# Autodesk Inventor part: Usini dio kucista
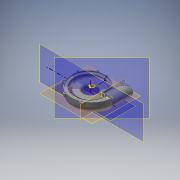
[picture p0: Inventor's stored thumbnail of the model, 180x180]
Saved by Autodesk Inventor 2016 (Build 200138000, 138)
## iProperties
Created: 2015-03
Part Number: Usini dio kucista
Material: Generic
Document SubType Name: Modeling
Designer: Uglješa
Density: 1 g/cm^3
Appearance: Default
Mass: 1245.57 g
Surface Area: 2848.36 cm^2
Volume: 1245.57 cm^3
Author: Uglješa
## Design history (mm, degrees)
sketch "Sketch1"
  geometry: L1 (0, 36.378)-(0, -65.866) reference; L2 (105, -10)-(105, 10); L3 (105, 10)-(102, 10); L4 (102, 10)-(102, 2); L5 (102, 2)-(90, 2); L6 (90, 2)-(90, -2); L7 (51.654, -17)-(51.654, -12); L8 (51.654, -17)-(80, -17); L9 (83.626, -12)-(51.654, -12); A1 r 13.48 centre (91.52, -10) between (80, -17) and (105, -10); A2 r 8.143 centre (91.52, -10) between (83.626, -12) and (90, -2); 1 further point
  constraints: 18 end point, 4 point on circle, 3 perpendicular, 2 centre point, 1 coincident, 1 horizontal, 1 parallel, 1 tangent, 1 vertical
  dimensions: "d25" = 8 distance between parallel lines of L3 L5; "d28" = 10 vertical distance of point (0, 0) A1.centre; "d151" = 12 distance from line of point (0, 0) L9; "d152" = 5 distance between parallel lines of L8 L9; "d344" = 15 distance between parallel lines of L6 L2; "d365" = 210 diameter of L2 L1; "d509" = 2 distance from line of point (0, 0) L5; "d514" = 4 distance of L5.end L6.end; "d616" = 25 distance from line of L2 L8.end; "d670" = 3 distance of L2.end L3.end
sketch "Sketch2"
  geometry: L1 (53.134, -17)-(80, -17); L2 (0, 0)-(0, -94.804) reference; L3 (53.134, -12)-(86.237, -12); L4 (120, -16)-(120, -0.062); L5 (103, -2)-(103, 2); L6 (117, 10)-(120, 10); L7 (120, 10)-(120, -0.062); L8 (53.134, -12)-(53.134, -17); L9 (117, 10)-(117, 2); L10 (117, 2)-(103, 2); A1 r 14.32 centre (99.987, -16) between (86.237, -12) and (103, -2); A2 r 20.013 centre (99.987, -16) between (80, -17) and (120, -16)
  constraints: 20 end point, 4 point on circle, 3 perpendicular, 2 centre point, 1 coincident, 1 collinear, 1 parallel, 1 tangent, 1 vertical
  dimensions: "d39" = 12 distance from line of L3 L2.start; "d42" = 5 distance between parallel lines of L3 L1; "d50" = 16 vertical distance of L2.start A1.centre; "d184" = 17 distance between parallel lines of L7 L5; "d350" = 2 distance from line of L2.start L10; "d351" = 8 distance between parallel lines of L6 L10; "d364" = 240 diameter of L4 L2; "d513" = 4 distance of L5.start L5.end; "d617" = 40 distance from line of L4 L1.end; "d671" = 3 distance of L6.start L6.end
sketch "Sketch3"
  geometry: L1 (0, -126.8)-(0, 28.645) reference; L2 (-61.778, -17)-(-75, -17); L3 (-61.778, -12)-(-84.03, -12); L4 (-130, -22)-(-130, 10); L5 (-108, -2)-(-108, 2); L6 (-108, 2)-(-127, 2); L7 (-127, 2)-(-127, 10); L8 (-127, 10)-(-130, 10); L9 (-61.778, -12)-(-61.778, -17); A1 r 27.727 centre (-102.273, -22) between (-130, -22) and (-75, -17); A2 r 20.804 centre (-102.273, -22) between (-108, -2) and (-84.03, -12); 1 further point
  constraints: 18 end point, 4 point on circle, 3 perpendicular, 3 vertical, 2 centre point, 2 parallel, 1 coincident, 1 tangent
  dimensions: "d62" = 5 distance between parallel lines of L2 L3; "d64" = 12 distance from line of point (0, 0) L3; "d70" = 8 distance of L6.end L7.end; "d72" = 2 distance from line of L6 point (0, 0); "d74" = 22 vertical distance of point (0, 0) A1.centre; "d186" = 22 distance between parallel lines of L4 L5; "d368" = 260 diameter of L4 L1; "d515" = 4 distance of L5.start L5.end; "d618" = 55 distance from line of L4 L2.end; "d678" = 3 distance of L7.end L4.end
sketch "Sketch4"
  geometry: L1 (0, 0)-(0, 390.533); L2 (0, 0)-(-377.579, 0); L3 (-120, 0)-(-120, -351.799); L4 (0, 105)-(221.176, 105); A1 r 105.938 centre (-14.063, 0) between (0, 105) and (-120, 0)
  constraints: 8 end point, 2 point on circle, 2 point on line, 2 vertical, 1 centre point, 1 horizontal, 1 perpendicular, 1 tangent
  dimensions: "d359" = 105 distance of L4.start L1.start; "d363" = 120 distance of L3.start L1.start
sketch "Sketch7"
  geometry: L1 (0, 0)-(0, -210.072); L2 (-140, -30)-(-140, 10); L3 (-140, 10)-(-137, 10); L4 (-137, 10)-(-137, 2); L5 (-137, 2)-(-106.2, 2); L6 (-106.2, 2)-(-106.2, -2); L7 (-84.752, -12)-(-48.748, -12); L8 (-48.748, -12)-(-48.748, -17); L9 (-48.748, -17)-(-75, -17); A1 r 33.8 centre (-106.2, -30) between (-140, -30) and (-75, -17); A2 r 28 centre (-106.2, -30) between (-106.2, -2) and (-84.752, -12)
  constraints: 18 end point, 4 parallel, 4 point on circle, 3 perpendicular, 2 centre point, 2 vertical, 1 coincident, 1 point on line, 1 tangent
  dimensions: "d102" = 8 distance of L3.end L4.end; "d103" = 28 radius of A2; "d207" = 2 vertical distance of L1.start L6.end; "d209" = 5 distance of L7.end L8.end; "d210" = 12 distance from line of L1.start L7; "d375" = 280 diameter of L2 L1; "d516" = 22 distance between parallel lines of L3 L7; "d619" = 65 distance from line of L9.end L2; "d679" = 3 distance of L2.end L3.end
loft "Loft4" dims "d672" = 10, "d673" = 90 deg, "d674" = 10, "d675" = 90 deg, "d676" = 0, "d677" = 90 deg
sketch "Sketch11"
  geometry: L1 (40, -27)-(40, -39.604); L2 (50, -42)-(55, -42); L3 (55, -42)-(55, -22); L4 (60, -17)-(77.651, -17); L5 (55, -12)-(77.651, -12); L6 (0, 0)-(0, -85.323); L7 (77.651, -17)-(77.651, -12); L8 (50, -60)-(48, -60); L9 (50, -60)-(50, -42); A1 r 30 centre (70, -39.604) between (40, -39.604) and (48, -60); A2 r 15 centre (55, -27) between (55, -12) and (40, -27); A3 r 5 centre (60, -22) between (60, -17) and (55, -22); 1 further point
  constraints: 18 end point, 6 point on circle, 5 tangent, 3 centre point, 2 parallel, 2 perpendicular, 2 point on line, 2 vertical, 1 horizontal
  dimensions: "d136" = 5 distance between parallel lines of L5 L4; "d138" = 15 radius of A2; "d139" = 80 diameter of L1 L6; "d141" = 30 radius of A1; "d144" = 17 distance from line of L6.start L4; "d193" = 5 radius of A3; "d414" = 18 distance between parallel lines of L2 L8; "d416" = 100 diameter of L9 L6; "d417" = 42 distance from line of L6.start L2; "d418" = 2 distance of L8.start L8.end; "d662" = 5 distance between parallel lines of L9 L3
sketch "Sketch12"
  geometry: L1 (-120, 0)-(-120, 196.1); L2 (0, 0)-(0, 238.053); A1 r 130.417 centre (10.417, 0) between (-120, 0) and (0, -130)
  constraints: 4 end point, 2 point on circle, 2 vertical, 1 centre point, 1 point on line, 1 tangent
  dimensions: "d369" = 130 distance of A1.end L2.start; "d370" = 120 distance of L2.start L1.start; "d371" = 120 distance from line of L2.start L1
loft "Loft5" sketch "Sketch12" dims "d187" = 0, "d188" = 90 deg, "d189" = 0, "d190" = 90 deg, "d372" = 0, "d373" = 90 deg
sketch "Sketch13"
  geometry: L1 (0, 0)-(185.048, 0); L2 (0, 0)-(0, -182.275); L3 (0, 0)-(487.793, 0); L4 (0, 0)-(0, -482.564); L5 (140, 0)-(140, 388.334); A1 r 130.357 centre (9.643, 0) between (0, -130) and (140, 0); 2 further points
  constraints: 10 end point, 4 point on line, 2 horizontal, 2 point on circle, 2 vertical, 1 centre point, 1 perpendicular, 1 tangent
  dimensions: "d376" = 140 distance of L1.start L5.start; "d377" = 130 distance of L1.start A1.start
workplane "Work Plane3"
workplane "Work Plane6"
sketch "Sketch34"
  geometry: L1 (113.093, 65.922)-(96.417, 49.246); L2 (47.171, 85.264)-(47.171, 65.141); L3 (92.893, -45.721)-(111.926, -64.755); L4 (47.171, -67.337)-(47.171, -94.636); L5 (-0.858, -48.029)-(-16.786, -63.958); L6 (47.171, 0)-(331.223, 0); L7 (-2.517, 49.689)-(1.756, 45.416); L8 (-27.461, 0)-(-54.951, 0); L9 (47.171, 0)-(-109.659, 0); L10 (144.214, 0)-(113.093, 0)
  constraints: 20 end point, 9 point on line, 2 horizontal, 2 perpendicular, 1 vertical
  dimensions: "d262" = 45 deg angle of L1 L6; "d263" = 45 deg angle of L1 L2; "d264" = 45 deg angle of L5 L4; "d265" = 45 deg angle of L2 L7
loft "Loft8" dims "d378" = 0, "d379" = 90 deg, "d380" = 0, "d381" = 90 deg, "d382" = 0, "d383" = 90 deg
  node "Edges3"
revolve "Revolution3" stored, may be unused: angle "d419" = 90 deg
sketch "Sketch55"
  geometry: L1 (55, -22)-(55, -42) reference; L2 (55, -30)-(102.194, -23.367); L3 (55, -30)-(55, -22); L4 (55, -22)-(100, -22); A1 r 15 centre (109, -10) between (100, -22) and (119.658, -20.555) reference; A2 r 15 centre (109, -10) between (100, -22) and (102.194, -23.367); 1 further point
  constraints: 6 end point, 3 point on circle, 1 centre point, 1 concentric, 1 horizontal, 1 point on line, 1 vertical
  dimensions: "d460" = 8 distance from line of L4 L2.start; "d461" = 8 deg angle of L4 L2
workplane "Work Plane14"
fillet "Fillet22" dims "d480" = 2
chamfer "Chamfer2" distance "d481" = 2; stored, may be unused: second distance "d482" = 2, angle "d483" = 45 deg
workplane "Work Plane15"
sketch "Sketch59"
  geometry: L1 (0, 0)-(0, 270.285); L2 (0, 0)-(203.327, 0); L3 (140, 0)-(139.966, 78); L4 (139.966, 78)-(141.966, 80); L5 (736.882, 1.819)-(736.828, 125); L6 (106.2, 0)-(106.2, 152.997); L7 (137.474, 120)-(144.101, 120); L8 (139.759, 105)-(145.151, 105); L9 (78.2, 0)-(134.2, 0) reference; L10 (134.2, 0)-(134.2, 130); L11 (134.2, 130)-(141.944, 130); L12 (141.966, 80)-(141.956, 102.042); L13 (141.954, 107.958)-(141.95, 117.042); L14 (141.947, 122.958)-(141.944, 130); L15 (134.2, 0)-(140, 0); A1 r 3 centre (142.448, 120) between (141.947, 122.958) and (141.95, 117.042); A2 r 3 centre (142.455, 105) between (141.954, 107.958) and (141.956, 102.042); 3 further points; 1 other entity
  constraints: 28 end point, 5 parallel, 4 point on circle, 3 collinear, 3 vertical, 2 centre point, 2 point on line, 1 horizontal, 1 midpoint, 1 perpendicular, 2 other
  dimensions: "d492" = 2 horizontal distance of L3.end L4.end; "d493" = 2 horizontal distance of L3.end L4.end; "d495" = 250 diameter of L5.end L2; "d623" = 3 radius of A2; "d624" = 3 radius of A1; "d629" = 130 distance from line of L11 L3.start; "d631" = 0 deg angle of L11 L7; "d632" = 10 distance from line of L11 L7.end; "d633" = 25 distance from line of L11 L8.end; "d634" = 50 distance from line of L11 L4.end; "d635" = 0.5 distance from line of L13 A2.centre; "d636" = 0.5 distance from line of L14 A1.centre
revolve "Revolution4" sketch "Sketch59" stored, may be unused: angle "d498" = 90 deg
sketch "Sketch62"
  geometry: L1 (-153, 8)-(-63.5, 8) reference; L2 (-51.5, 8)-(-63.5, 8) reference; L3 (-153, 8)-(-51.5, 8) reference; L4 (-153, 8)-(-288, 8) reference; L5 (-288, 8)-(-153, 8) reference; L6 (-153, 8)-(0, 8) reference; L7 (-12.122, 8)-(0, 8) reference; L8 (-12.122, 8)-(-13.881, 8) reference; L9 (-13.881, 8)-(-20.97, 8) reference; L10 (-153, 8)-(-20.97, 8) reference; L11 (-153, 8)-(-276, 8) reference; L12 (-153, 8)-(-276, 8) reference; L13 (-30.8, 8)-(0, 8) reference; L14 (-2.155, 8)-(-44.654, 8); L15 (-44.654, 8)-(-44.654, -28.051); L16 (-44.654, -28.051)-(-2.155, -28.051); L17 (-2.155, -28.051)-(-2.155, 8); 2 further points
  constraints: 8 end point, 2 parallel, 1 horizontal, 1 perpendicular, 1 point on line
extrude "Extrusion7" cut sketch "Sketch62" distance "d517" = 20; taper "d518" = 0 deg
workplane "Work Plane20"
workplane "Work Plane23"
sketch "Sketch63"
  geometry: L1 (-7.774, 7.255)-(180.406, 7.255); L2 (-7.774, 7.255)-(-264.35, 7.255); L3 (-53.15, -123.454)-(-51.856, -118.625); L4 (-51.856, -118.625)-(-32.537, -123.801); L5 (-33.831, -128.631)-(-32.537, -123.801); L6 (-125.357, -49.084)-(-121.027, -46.584); L7 (-121.027, -46.584)-(-111.027, -63.905); L8 (-115.357, -66.405)-(-111.027, -63.905); L9 (-125.926, 49.267)-(-121.096, 47.973); L10 (-121.096, 47.973)-(-126.273, 28.654); L11 (-131.102, 29.948)-(-126.273, 28.654); L12 (-60.113, 117.91)-(-57.613, 113.58); L13 (-57.613, 113.58)-(-74.934, 103.58); L14 (-77.434, 107.91)-(-74.934, 103.58); L15 (31.391, 114.783)-(30.097, 109.953); L16 (30.097, 109.953)-(10.778, 115.129); L17 (12.073, 119.959)-(10.778, 115.129); L18 (-7.774, 7.255)-(36.411, 172.155); L19 (-7.774, 7.255)-(-95.441, 159.1); L20 (-7.774, 7.255)-(-180.234, 53.466); L21 (-7.774, 7.255)-(-169.432, -86.078); L22 (-7.774, 7.255)-(-59.857, -187.122); L23 (-7.774, 7.255)-(86.188, -155.491); A1 r 10 centre (-43.491, -126.042) between (-53.15, -123.454) and (-33.831, -128.631); A2 r 10 centre (-120.357, -57.745) between (-125.357, -49.084) and (-115.357, -66.405); A3 r 10 centre (-128.514, 39.608) between (-125.926, 49.267) and (-131.102, 29.948); A4 r 10 centre (-68.774, 112.91) between (-60.113, 117.91) and (-77.434, 107.91); A5 r 10 centre (21.732, 117.371) between (31.391, 114.783) and (12.073, 119.959)
  constraints: 46 end point, 14 perpendicular, 10 point on circle, 10 tangent, 5 centre point, 5 point on line, 2 horizontal
  dimensions: "d544" = 45 deg angle of L19 L18; "d545" = 45 deg angle of L20 L19; "d546" = 45 deg angle of L21 L20; "d547" = 45 deg angle of L22 L21; "d548" = 5 distance from line of A1.centre L4; "d549" = 0 deg angle of L3 L5; "d550" = 10 radius of A1; "d552" = 5 distance from line of A2.centre L7; "d555" = 10 radius of A3; "d556" = 5 distance from line of L10 A3.centre; "d558" = 10 radius of A4; "d559" = 5 distance from line of L13 A4.centre; "d561" = 10 radius of A5; "d563" = 5 distance from line of A5.centre L16; "d568" = 114 distance of L1.start A5.centre; "d569" = 122 distance of L1.start A4.centre; "d571" = 130 distance of A2.centre L1.start; "d572" = 138 distance of L1.start A1.centre; "d599" = 45 deg angle of L22 L23; "d611" = 120 distance from line of L1.start L10; "d731" = 10 radius of A2
extrude "Extrusion8" join sketch "Sketch63" distance "d526" = 20; taper "d527" = 0 deg
workplane "Work Plane22"
workplane "Work Plane21"
workplane "Work Plane24"
fillet "Fillet30" dims "d627" = 1
workplane "Work Plane19"
sketch "Sketch73"
  geometry: L1 (0, 36.378)-(0, -65.866) reference; L2 (-5, 20)-(-5, 40); L3 (-5, 40)-(-8, 40); L4 (-8, 40)-(-8, 32); L5 (-8, 32)-(-20, 32); L6 (-20, 32)-(-20, 28); L7 (-56.345, 13)-(-56.345, 18); L8 (-56.345, 13)-(-30, 13); L9 (-26.374, 18)-(-56.345, 18); L10 (54.915, 40)-(-65, 40) reference; A1 r 13.48 centre (-18.48, 20) between (-30, 13) and (-5, 20); A2 r 8.143 centre (-18.48, 20) between (-26.374, 18) and (-20, 28); 3 further points
  constraints: 20 end point, 4 point on circle, 3 perpendicular, 2 centre point, 2 horizontal, 1 coincident, 1 collinear, 1 parallel, 1 point on line, 1 tangent, 1 vertical, 3 other
  dimensions: "d638" = 8 distance between parallel lines of L3 L5; "d639" = 10 vertical distance of point (0, 30) A1.centre; "d640" = 12 distance from line of point (0, 30) L9; "d641" = 5 distance between parallel lines of L8 L9; "d642" = 15 distance between parallel lines of L6 L2; "d644" = 2 distance from line of point (0, 30) L5; "d645" = 12 distance between parallel lines of L6 L4; "d646" = 4 distance of L5.end L6.end; "d647" = 25 distance from line of L2 L8.end; "d650" = 5 distance from line of point (0, 30) L2
sketch "Sketch52"
  geometry: L1 (0, 0)-(265.787, 0); L2 (0, 0)-(0, 443.042); L3 (78.2, 557.858)-(78.2, -245.858) reference; L4 (78.2, 130)-(78.2, 0) reference; L5 (0, 83.626)-(0, 99.663) reference; A1 r 119.037 centre (-15.843, -12.978) between (78.2, 60) and (0, 105); 3 further points; 1 other entity
  constraints: 4 end point, 2 point on circle, 2 point on line, 1 centre point, 1 horizontal, 1 vertical, 2 other
  dimensions: "d390" = 105 distance of L1.start A1.end; "d637" = 60 vertical distance of L1.start A1.start
loft "Loft11" sketch "Sketch73", "Sketch52" dims "d651" = 0, "d652" = 90 deg, "d653" = 0, "d654" = 90 deg, "d655" = 0, "d656" = 90 deg
  node "Edges6"
sketch "Sketch65"
  geometry: A1 r 10 centre (23.604, 116.802) between (33.252, 114.174) and (13.955, 119.431) reference; A2 r 10 centre (-66.919, 112.72) between (-58.238, 117.683) and (-75.6, 107.756) reference; A3 r 10 centre (-126.966, 39.667) between (-124.337, 49.315) and (-129.594, 30.019) reference; A4 r 10 centre (-119.215, -57.719) between (-124.179, -49.037) and (-114.251, -66.4) reference; A5 r 10 centre (-42.634, -126.337) between (-52.283, -123.708) and (-32.986, -128.965) reference
hole "Hole2" sketch "Sketch65" at (23.604, 116.802), (-66.919, 112.72), (-126.966, 39.667), (-119.215, -57.719), (-42.634, -126.337) diameter "d580" = 9; stored, may be unused: countersink angle "d584" = 90 deg, drill point angle "d586" = 118 deg; dims "d581" = 6, "d582" = 24, "d583" = 6.3, "d585" = 10
sketch "Sketch74"
  geometry: L1 (54, 40)-(-65, 40) reference; L2 (-5, 40)-(-65, 40); L3 (-65, 40)-(-65, 7); L4 (-65, 7)-(-10, 7); L5 (-5, 12)-(-5, 40); L6 (-5, 12)-(-10, 12); L7 (-10, 12)-(-10, 7); L8 (-65, 18)-(-65, 33.8) reference; 5 further points; 2 other entities
  constraints: 14 end point, 3 horizontal, 2 parallel, 2 perpendicular, 1 point on line, 4 other
  dimensions: "d659" = 33 distance between parallel lines of L1 L4; "d660" = 5 distance of L6.end L4.end; "d661" = 5 distance of L5.start L6.end
extrude "Extrusion11" join sketch "Sketch74" distance "d657" = 2; taper "d658" = 0 deg
sketch "Sketch75"
  geometry: L1 (-30, -14)-(-21.448, -14) reference; L2 (0, -4)-(0, 0) reference; L3 (0, 0)-(10.883, 0) reference; L4 (-28, 8)-(-28, -13.067) reference; L5 (-28, 8)-(-30, 8) reference; L6 (-30, -14)-(-30, 8) reference; L7 (-30, 8)-(33, 8); L8 (33, 8)-(33, 0); L9 (33, 0)-(0, 0); A1 r 28 centre (0, -32) between (0, -4) and (-21.448, -14) reference; A2 r 33.8 centre (0, -32) between (10.883, 0) and (-28, -13.067) reference; 1 further point
  constraints: 6 end point, 2 perpendicular, 1 point on line
  dimensions: "d667" = 63 distance of L5.end L7.end
extrude "Extrusion12" join sketch "Sketch75" distance "d664" = 2; taper "d665" = 0 deg
workplane "Work Plane25"
fillet "Fillet34" dims "d708" = 10
fillet "Fillet35" dims "d709" = 10
fillet "Fillet36" dims "d710" = 10
fillet "Fillet38" dims "d712" = 5
fillet "Fillet39" dims "d713" = 5
fillet "Fillet41" dims "d715" = 6
fillet "Fillet43" dims "d717" = 5
fillet "Fillet46" dims "d727" = 5
fillet "Fillet48" dims "d729" = 2
fillet "Fillet49" dims "d730" = 2
workplane "Work Plane26"
sketch "Sketch79"
  geometry: L1 (-178.2, 2.541)-(-178.2, 74.293); L2 (-178.2, 74.293)-(-166.2, 74.293); L3 (-166.2, 74.293)-(-166.2, 2.541); L4 (-166.2, 2.541)-(-178.2, 2.541); L5 (-138.2, 130)-(-194.2, 130) reference; L6 (-200.259, 78.293)-(-132.141, 78.293) reference; L7 (-166.2, 130)-(-166.2, -187.613); 3 further points
  constraints: 2 end point, 1 collinear, 1 midpoint, 1 point on line, 1 vertical, 2 other
  dimensions: "d733" = 12 distance of L2.end L1.end; "d740" = 4 distance between parallel lines of L6 L2
emboss "Emboss6" sketch "Sketch79" dims "d62" = 5, "d737" = 1, "d738" = 0
body "Solid2"
node "Projected Loop3"
other parameters: "d26" = 12, "d37" = 15, "d625" = 0.5, "d626" = 0.5, "d680" = 5, "d732" = 46.8
